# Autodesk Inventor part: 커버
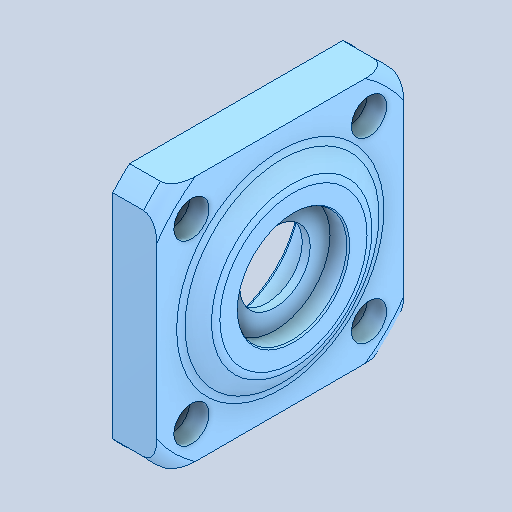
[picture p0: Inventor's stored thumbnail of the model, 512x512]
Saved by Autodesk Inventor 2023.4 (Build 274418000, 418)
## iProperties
Created: 2024-10
Part Number: 커버
Material: 알루미늄 6061
Document SubType Name: Modeling
Designer: EDU
Density: 2.7 g/cm^3
Appearance: 기본값
Author: jhkim
Sending System: Autodesk Inventor 2025
Preprocessor: ST-DEVELOPER v20
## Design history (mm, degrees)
feature "솔리드1"
node "솔리드2"
